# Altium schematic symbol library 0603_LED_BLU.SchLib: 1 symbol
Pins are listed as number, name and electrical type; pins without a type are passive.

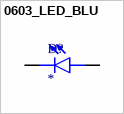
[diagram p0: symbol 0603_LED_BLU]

## 0603_LED_BLU
designator D?
MF: Wurth Elektronik; MP: 150060VS75000
footprint 0603_LED
pins: 1 NEG, 2 POS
